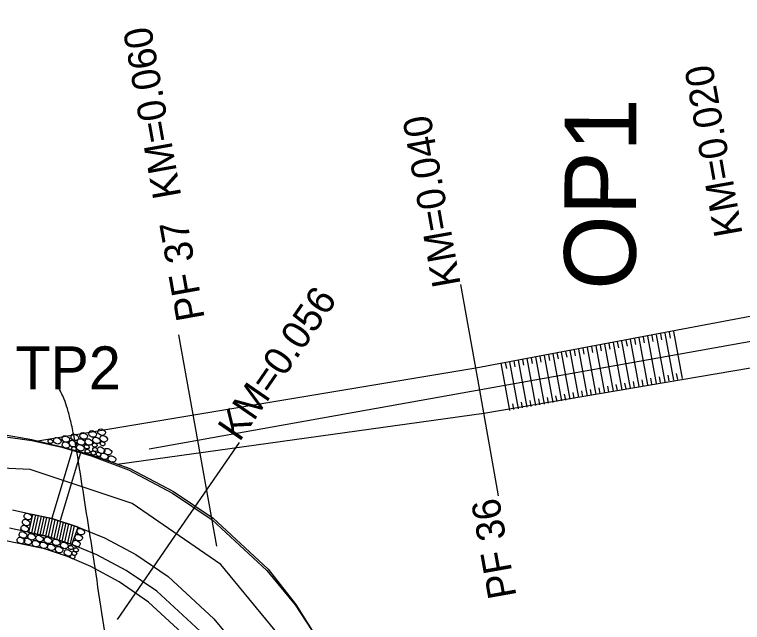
# Model space of a CAD drawing. Extents: x -478102 to -473059, y -1117705 to -1114104.
# Drawn here: x -476287.7 to -476236.8, y -1117055.2 to -1117012.7 of the extents above; entities that cross this region are included whole.
import ezdxf

# ---------------------------------------------------------------- set-up
doc = ezdxf.new("R2010")
doc.units = 0
for name, color, linetype in [('cesty', 7, 'Continuous'), ('el_vedeni__VN', 7, 'Continuous'), ('POLYGONY_SITUACE_PF', 7, 'Continuous'), ('POLYGONY_SITUACE_PF_POPISY', 7, 'Continuous'), ('POLYGONY_SITUACE_PO', 7, 'Continuous'), ('TP _navrh', 7, 'Continuous'), ('TP_HS', 7, 'Continuous'), ('Vrstevnice_hlavni', 7, 'Continuous'), ('Vrstevnice_vedlejsi', 7, 'Continuous')]:
    doc.layers.add(name, color=color, linetype=linetype)

msp = doc.modelspace()

# ---------------------------------------------------------------- linework, layer by layer
for p, q in [((-476285.04, -1117047.856), (-476283.635, -1117043.126)), ((-476284.465, -1117048.027), (-476283.06, -1117043.297)), ((-476286.418, -1117047.609), (-476286.693, -1117048.868)), ((-476286.222, -1117047.651), (-476286.498, -1117048.911)), ((-476286.027, -1117047.694), (-476286.302, -1117048.954)), ((-476285.831, -1117047.737), (-476286.107, -1117048.996)), ((-476285.636, -1117047.78), (-476285.912, -1117049.039)), ((-476285.441, -1117047.822), (-476285.716, -1117049.082)), ((-476285.245, -1117047.865), (-476285.521, -1117049.125)), ((-476285.05, -1117047.908), (-476285.325, -1117049.167)), ((-476284.858, -1117047.965), (-476285.13, -1117049.21)), ((-476284.667, -1117048.027), (-476284.944, -1117049.294)), ((-476284.476, -1117048.09), (-476284.753, -1117049.356)), ((-476284.284, -1117048.152), (-476284.561, -1117049.419)), ((-476284.093, -1117048.214), (-476284.37, -1117049.481)), ((-476283.902, -1117048.276), (-476284.179, -1117049.543)), ((-476283.711, -1117048.338), (-476283.988, -1117049.605)), ((-476283.52, -1117048.401), (-476283.797, -1117049.667))]:
    msp.add_line(p, q)
for points in [[(-476243.78, -1117035.233), (-476243.704, -1117035.643)], [(-476243.479, -1117035.177), (-476242.873, -1117038.464)], [(-476243.178, -1117035.122), (-476243.102, -1117035.532)], [(-476242.877, -1117035.066), (-476242.271, -1117038.353)], [(-476242.576, -1117035.011), (-476242.5, -1117035.422)], [(-476242.275, -1117034.955), (-476241.669, -1117038.242)], [(-476241.974, -1117034.9), (-476241.899, -1117035.311)], [(-476241.673, -1117034.844), (-476241.067, -1117038.131)], [(-476246.488, -1117035.732), (-476245.882, -1117039.018)], [(-476246.187, -1117035.676), (-476246.111, -1117036.087)], [(-476245.886, -1117035.621), (-476245.28, -1117038.907)], [(-476245.585, -1117035.566), (-476245.509, -1117035.976)], [(-476245.284, -1117035.51), (-476244.678, -1117038.796)], [(-476244.983, -1117035.455), (-476244.908, -1117035.865)], [(-476244.682, -1117035.399), (-476244.077, -1117038.685)], [(-476244.382, -1117035.344), (-476244.306, -1117035.754)], [(-476244.081, -1117035.288), (-476243.475, -1117038.574)], [(-476249.196, -1117036.231), (-476249.12, -1117036.642)], [(-476248.895, -1117036.176), (-476248.289, -1117039.462)], [(-476248.594, -1117036.12), (-476248.518, -1117036.531)], [(-476248.293, -1117036.065), (-476247.687, -1117039.351)], [(-476247.992, -1117036.009), (-476247.917, -1117036.42)], [(-476247.691, -1117035.954), (-476247.086, -1117039.24)], [(-476247.391, -1117035.898), (-476247.315, -1117036.309)], [(-476247.09, -1117035.843), (-476246.484, -1117039.129)], [(-476246.789, -1117035.787), (-476246.713, -1117036.198)], [(-476251.904, -1117036.731), (-476251.298, -1117040.017)], [(-476251.603, -1117036.675), (-476251.527, -1117037.086)], [(-476251.302, -1117036.62), (-476250.696, -1117039.906)], [(-476251.001, -1117036.564), (-476250.926, -1117036.975)], [(-476250.701, -1117036.509), (-476250.095, -1117039.795)], [(-476250.4, -1117036.453), (-476250.324, -1117036.864)], [(-476250.099, -1117036.398), (-476249.493, -1117039.684)], [(-476249.798, -1117036.342), (-476249.722, -1117036.753)], [(-476249.497, -1117036.287), (-476248.891, -1117039.573)], [(-476253.71, -1117037.063), (-476253.104, -1117040.35)], [(-476253.409, -1117037.008), (-476253.333, -1117037.419)], [(-476253.108, -1117036.952), (-476252.502, -1117040.239)], [(-476252.807, -1117036.897), (-476252.731, -1117037.308)], [(-476252.506, -1117036.842), (-476251.9, -1117040.128)], [(-476252.205, -1117036.786), (-476252.129, -1117037.197)], [(-476241.368, -1117038.186), (-476241.444, -1117037.775)], [(-476243.776, -1117038.63), (-476243.851, -1117038.219)], [(-476243.174, -1117038.519), (-476243.25, -1117038.108)], [(-476242.572, -1117038.408), (-476242.648, -1117037.997)], [(-476241.97, -1117038.297), (-476242.046, -1117037.886)], [(-476246.785, -1117039.185), (-476246.86, -1117038.774)], [(-476246.183, -1117039.074), (-476246.259, -1117038.663)], [(-476245.581, -1117038.963), (-476245.657, -1117038.552)], [(-476244.979, -1117038.852), (-476245.055, -1117038.441)], [(-476244.377, -1117038.741), (-476244.453, -1117038.33)], [(-476249.192, -1117039.629), (-476249.268, -1117039.218)], [(-476248.59, -1117039.518), (-476248.666, -1117039.107)], [(-476247.988, -1117039.407), (-476248.064, -1117038.996)], [(-476247.386, -1117039.296), (-476247.462, -1117038.885)], [(-476252.201, -1117040.183), (-476252.277, -1117039.773)], [(-476251.599, -1117040.072), (-476251.675, -1117039.662)], [(-476250.997, -1117039.961), (-476251.073, -1117039.551)], [(-476250.396, -1117039.85), (-476250.471, -1117039.44)], [(-476249.794, -1117039.74), (-476249.869, -1117039.329)], [(-476252.803, -1117040.294), (-476252.878, -1117039.883)]]:
    msp.add_lwpolyline(points)
msp.add_lwpolyline([(-476285.005, -1117047.917), (-476286.418, -1117047.609), (-476286.693, -1117048.868), (-476285.356, -1117049.16), (-476283.675, -1117049.707), (-476283.228, -1117048.496)], close=True)
for points in [[(-476282.414, -1117041.798), (-476282.487, -1117042.014), (-476282.247, -1117042.215), (-476282.036, -1117042.166), (-476281.955, -1117041.994), (-476282.052, -1117041.865), (-476282.341, -1117041.771), (-476282.414, -1117041.798)], [(-476281.786, -1117041.678), (-476281.859, -1117041.894), (-476281.62, -1117042.094), (-476281.409, -1117042.046), (-476281.327, -1117041.874), (-476281.424, -1117041.745), (-476281.713, -1117041.651), (-476281.786, -1117041.678)], [(-476285.292, -1117042.386), (-476285.338, -1117042.524), (-476285.185, -1117042.653), (-476285.05, -1117042.622), (-476284.998, -1117042.512), (-476285.06, -1117042.429), (-476285.245, -1117042.369), (-476285.292, -1117042.386)], [(-476284.885, -1117042.281), (-476284.958, -1117042.497), (-476284.719, -1117042.697), (-476284.508, -1117042.649), (-476284.427, -1117042.477), (-476284.523, -1117042.347), (-476284.812, -1117042.254), (-476284.885, -1117042.281)], [(-476284.287, -1117042.149), (-476284.36, -1117042.365), (-476284.121, -1117042.566), (-476283.91, -1117042.517), (-476283.829, -1117042.345), (-476283.925, -1117042.216), (-476284.215, -1117042.122), (-476284.287, -1117042.149)], [(-476283.66, -1117042.038), (-476283.733, -1117042.254), (-476283.494, -1117042.455), (-476283.283, -1117042.406), (-476283.201, -1117042.235), (-476283.298, -1117042.105), (-476283.587, -1117042.011), (-476283.66, -1117042.038)], [(-476283.228, -1117042.361), (-476283.301, -1117042.577), (-476283.062, -1117042.778), (-476282.851, -1117042.73), (-476282.769, -1117042.558), (-476282.866, -1117042.428), (-476283.155, -1117042.335), (-476283.228, -1117042.361)], [(-476283.041, -1117041.936), (-476283.114, -1117042.153), (-476282.875, -1117042.353), (-476282.664, -1117042.305), (-476282.583, -1117042.133), (-476282.679, -1117042.003), (-476282.969, -1117041.91), (-476283.041, -1117041.936)], [(-476282.681, -1117042.361), (-476282.754, -1117042.577), (-476282.515, -1117042.778), (-476282.304, -1117042.73), (-476282.223, -1117042.558), (-476282.319, -1117042.428), (-476282.609, -1117042.335), (-476282.681, -1117042.361)], [(-476282.146, -1117042.25), (-476282.219, -1117042.467), (-476281.98, -1117042.667), (-476281.769, -1117042.619), (-476281.687, -1117042.447), (-476281.784, -1117042.317), (-476282.073, -1117042.224), (-476282.146, -1117042.25)], [(-476281.647, -1117042.14), (-476281.72, -1117042.356), (-476281.481, -1117042.556), (-476281.27, -1117042.508), (-476281.189, -1117042.336), (-476281.285, -1117042.206), (-476281.575, -1117042.113), (-476281.647, -1117042.14)], [(-476284.278, -1117042.574), (-476284.351, -1117042.79), (-476284.112, -1117042.99), (-476283.901, -1117042.942), (-476283.82, -1117042.77), (-476283.916, -1117042.641), (-476284.205, -1117042.547), (-476284.278, -1117042.574)], [(-476283.798, -1117042.472), (-476283.871, -1117042.688), (-476283.632, -1117042.889), (-476283.421, -1117042.841), (-476283.34, -1117042.669), (-476283.436, -1117042.539), (-476283.725, -1117042.445), (-476283.798, -1117042.472)], [(-476283.641, -1117042.903), (-476283.687, -1117043.042), (-476283.534, -1117043.17), (-476283.399, -1117043.139), (-476283.347, -1117043.029), (-476283.409, -1117042.946), (-476283.594, -1117042.886), (-476283.641, -1117042.903)], [(-476283.272, -1117042.768), (-476283.345, -1117042.984), (-476283.106, -1117043.184), (-476282.895, -1117043.136), (-476282.813, -1117042.964), (-476282.91, -1117042.834), (-476283.199, -1117042.741), (-476283.272, -1117042.768)], [(-476282.76, -1117042.766), (-476282.807, -1117042.904), (-476282.653, -1117043.033), (-476282.518, -1117043.002), (-476282.466, -1117042.892), (-476282.528, -1117042.809), (-476282.713, -1117042.749), (-476282.76, -1117042.766)], [(-476282.195, -1117042.645), (-476282.242, -1117042.783), (-476282.089, -1117042.911), (-476281.954, -1117042.88), (-476281.902, -1117042.77), (-476281.964, -1117042.687), (-476282.149, -1117042.628), (-476282.195, -1117042.645)], [(-476281.647, -1117042.55), (-476281.694, -1117042.688), (-476281.541, -1117042.816), (-476281.406, -1117042.785), (-476281.353, -1117042.675), (-476281.415, -1117042.592), (-476281.6, -1117042.533), (-476281.647, -1117042.55)], [(-476282.707, -1117043.083), (-476282.754, -1117043.221), (-476282.601, -1117043.349), (-476282.466, -1117043.319), (-476282.414, -1117043.209), (-476282.475, -1117043.126), (-476282.661, -1117043.066), (-476282.707, -1117043.083)], [(-476282.29, -1117043.199), (-476282.337, -1117043.337), (-476282.184, -1117043.466), (-476282.049, -1117043.435), (-476281.997, -1117043.325), (-476282.059, -1117043.242), (-476282.244, -1117043.182), (-476282.29, -1117043.199)], [(-476282.169, -1117042.961), (-476282.216, -1117043.1), (-476282.063, -1117043.228), (-476281.928, -1117043.197), (-476281.876, -1117043.087), (-476281.937, -1117043.004), (-476282.123, -1117042.944), (-476282.169, -1117042.961)], [(-476281.926, -1117043.296), (-476281.972, -1117043.434), (-476281.819, -1117043.562), (-476281.684, -1117043.531), (-476281.632, -1117043.421), (-476281.694, -1117043.338), (-476281.879, -1117043.279), (-476281.926, -1117043.296)], [(-476281.823, -1117042.934), (-476281.896, -1117043.15), (-476281.657, -1117043.351), (-476281.446, -1117043.302), (-476281.364, -1117043.13), (-476281.461, -1117043.001), (-476281.75, -1117042.907), (-476281.823, -1117042.934)], [(-476281.601, -1117043.359), (-476281.674, -1117043.575), (-476281.435, -1117043.775), (-476281.224, -1117043.727), (-476281.143, -1117043.555), (-476281.239, -1117043.426), (-476281.529, -1117043.332), (-476281.601, -1117043.359)], [(-476281.352, -1117043.036), (-476281.425, -1117043.252), (-476281.186, -1117043.452), (-476280.975, -1117043.404), (-476280.894, -1117043.232), (-476280.99, -1117043.102), (-476281.279, -1117043.009), (-476281.352, -1117043.036)], [(-476281.061, -1117043.555), (-476281.134, -1117043.771), (-476280.895, -1117043.971), (-476280.684, -1117043.923), (-476280.602, -1117043.751), (-476280.699, -1117043.622), (-476280.988, -1117043.528), (-476281.061, -1117043.555)], [(-476287.061, -1117047.985), (-476287.134, -1117048.202), (-476286.895, -1117048.402), (-476286.684, -1117048.354), (-476286.603, -1117048.182), (-476286.699, -1117048.052), (-476286.988, -1117047.959), (-476287.061, -1117047.985)], [(-476286.94, -1117047.565), (-476287.013, -1117047.781), (-476286.774, -1117047.982), (-476286.563, -1117047.933), (-476286.482, -1117047.762), (-476286.578, -1117047.632), (-476286.867, -1117047.538), (-476286.94, -1117047.565)], [(-476287.155, -1117048.405), (-476287.228, -1117048.621), (-476286.988, -1117048.821), (-476286.777, -1117048.773), (-476286.696, -1117048.601), (-476286.793, -1117048.471), (-476287.082, -1117048.378), (-476287.155, -1117048.405)], [(-476287.276, -1117048.848), (-476287.349, -1117049.065), (-476287.11, -1117049.265), (-476286.899, -1117049.217), (-476286.817, -1117049.045), (-476286.914, -1117048.915), (-476287.203, -1117048.822), (-476287.276, -1117048.848)], [(-476286.681, -1117048.984), (-476286.754, -1117049.2), (-476286.514, -1117049.4), (-476286.304, -1117049.352), (-476286.222, -1117049.18), (-476286.319, -1117049.05), (-476286.608, -1117048.957), (-476286.681, -1117048.984)], [(-476283.241, -1117048.624), (-476283.314, -1117048.84), (-476283.075, -1117049.041), (-476282.864, -1117048.993), (-476282.782, -1117048.821), (-476282.879, -1117048.691), (-476283.168, -1117048.597), (-476283.241, -1117048.624)], [(-476287.429, -1117049.239), (-476287.502, -1117049.455), (-476287.263, -1117049.656), (-476287.052, -1117049.607), (-476286.97, -1117049.435), (-476287.067, -1117049.306), (-476287.356, -1117049.212), (-476287.429, -1117049.239)], [(-476286.944, -1117049.308), (-476287.017, -1117049.524), (-476286.777, -1117049.724), (-476286.566, -1117049.676), (-476286.485, -1117049.504), (-476286.582, -1117049.374), (-476286.871, -1117049.281), (-476286.944, -1117049.308)], [(-476286.379, -1117049.461), (-476286.452, -1117049.677), (-476286.213, -1117049.877), (-476286.002, -1117049.829), (-476285.921, -1117049.657), (-476286.017, -1117049.527), (-476286.307, -1117049.434), (-476286.379, -1117049.461)], [(-476286.126, -1117049.102), (-476286.199, -1117049.318), (-476285.96, -1117049.518), (-476285.749, -1117049.47), (-476285.668, -1117049.298), (-476285.764, -1117049.169), (-476286.053, -1117049.075), (-476286.126, -1117049.102)], [(-476285.53, -1117049.223), (-476285.603, -1117049.439), (-476285.364, -1117049.64), (-476285.153, -1117049.592), (-476285.072, -1117049.42), (-476285.168, -1117049.29), (-476285.457, -1117049.196), (-476285.53, -1117049.223)], [(-476284.96, -1117049.371), (-476285.033, -1117049.587), (-476284.794, -1117049.788), (-476284.583, -1117049.739), (-476284.502, -1117049.567), (-476284.598, -1117049.438), (-476284.888, -1117049.344), (-476284.96, -1117049.371)], [(-476283.552, -1117049.453), (-476283.625, -1117049.669), (-476283.386, -1117049.869), (-476283.175, -1117049.821), (-476283.094, -1117049.649), (-476283.19, -1117049.52), (-476283.479, -1117049.426), (-476283.552, -1117049.453)], [(-476283.399, -1117049.041), (-476283.472, -1117049.257), (-476283.233, -1117049.458), (-476283.022, -1117049.409), (-476282.941, -1117049.238), (-476283.037, -1117049.108), (-476283.326, -1117049.014), (-476283.399, -1117049.041)], [(-476285.841, -1117049.577), (-476285.914, -1117049.793), (-476285.675, -1117049.993), (-476285.464, -1117049.945), (-476285.383, -1117049.773), (-476285.479, -1117049.644), (-476285.769, -1117049.55), (-476285.841, -1117049.577)], [(-476285.303, -1117049.714), (-476285.376, -1117049.93), (-476285.137, -1117050.131), (-476284.926, -1117050.082), (-476284.845, -1117049.91), (-476284.941, -1117049.781), (-476285.231, -1117049.687), (-476285.303, -1117049.714)], [(-476284.755, -1117049.878), (-476284.828, -1117050.094), (-476284.589, -1117050.294), (-476284.378, -1117050.246), (-476284.296, -1117050.074), (-476284.393, -1117049.944), (-476284.682, -1117049.851), (-476284.755, -1117049.878)], [(-476284.391, -1117049.587), (-476284.464, -1117049.803), (-476284.225, -1117050.004), (-476284.014, -1117049.956), (-476283.932, -1117049.784), (-476284.029, -1117049.654), (-476284.318, -1117049.561), (-476284.391, -1117049.587)], [(-476283.869, -1117049.803), (-476283.915, -1117049.941), (-476283.762, -1117050.069), (-476283.627, -1117050.039), (-476283.575, -1117049.929), (-476283.637, -1117049.846), (-476283.822, -1117049.786), (-476283.869, -1117049.803)], [(-476283.511, -1117049.965), (-476283.558, -1117050.103), (-476283.405, -1117050.231), (-476283.27, -1117050.2), (-476283.218, -1117050.09), (-476283.28, -1117050.007), (-476283.465, -1117049.948), (-476283.511, -1117049.965)], [(-476284.138, -1117050.105), (-476284.211, -1117050.321), (-476283.971, -1117050.521), (-476283.76, -1117050.473), (-476283.679, -1117050.301), (-476283.775, -1117050.171), (-476284.065, -1117050.078), (-476284.138, -1117050.105)], [(-476283.74, -1117050.444), (-476283.787, -1117050.583), (-476283.634, -1117050.711), (-476283.499, -1117050.68), (-476283.447, -1117050.57), (-476283.509, -1117050.487), (-476283.694, -1117050.427), (-476283.74, -1117050.444)], [(-476283.624, -1117050.205), (-476283.671, -1117050.344), (-476283.518, -1117050.472), (-476283.383, -1117050.441), (-476283.33, -1117050.331), (-476283.392, -1117050.248), (-476283.577, -1117050.188), (-476283.624, -1117050.205)]]:
    msp.add_spline(points, degree=3)
at = {"layer": 'cesty'}
for p, q in [((-476288.604, -1117042.159), (-476286.477, -1117042.455)), ((-476288.59, -1117042.021), (-476286.463, -1117042.376)), ((-476286.477, -1117042.455), (-476284.378, -1117042.908)), ((-476286.463, -1117042.376), (-476284.374, -1117042.894)), ((-476284.378, -1117042.908), (-476282.318, -1117043.515)), ((-476284.374, -1117042.894), (-476282.3, -1117043.463)), ((-476282.318, -1117043.515), (-476279.727, -1117044.491)), ((-476282.3, -1117043.463), (-476279.635, -1117044.419)), ((-476279.727, -1117044.491), (-476276.645, -1117046.126)), ((-476279.635, -1117044.419), (-476276.577, -1117046.014)), ((-476276.645, -1117046.126), (-476273.889, -1117047.998)), ((-476276.577, -1117046.014), (-476273.801, -1117047.883)), ((-476287.83, -1117047.3), (-476285.005, -1117047.917)), ((-476285.005, -1117047.917), (-476283.228, -1117048.496)), ((-476273.801, -1117047.883), (-476269.975, -1117051.447)), ((-476273.889, -1117047.998), (-476270.059, -1117051.524)), ((-476285.356, -1117049.16), (-476288.03, -1117048.576)), ((-476283.228, -1117048.496), (-476281.395, -1117049.259)), ((-476283.675, -1117049.707), (-476285.356, -1117049.16)), ((-476281.395, -1117049.259), (-476279.216, -1117050.416)), ((-476281.942, -1117050.429), (-476283.675, -1117049.707)), ((-476279.879, -1117051.525), (-476281.942, -1117050.429)), ((-476279.216, -1117050.416), (-476276.946, -1117051.958)), ((-476269.975, -1117051.447), (-476268.033, -1117053.896)), ((-476277.732, -1117052.983), (-476279.879, -1117051.525)), ((-476276.946, -1117051.958), (-476273.752, -1117054.898)), ((-476270.059, -1117051.524), (-476268.093, -1117053.939)), ((-476274.708, -1117055.766), (-476277.732, -1117052.983)), ((-476268.093, -1117053.939), (-476266.552, -1117056.287)), ((-476268.033, -1117053.896), (-476266.535, -1117056.277)), ((-476273.752, -1117054.898), (-476272.135, -1117056.886))]:
    msp.add_line(p, q, dxfattribs=at)
msp.add_lwpolyline([(-476266.732, -1117074.511), (-476270.768, -1117064.204), (-476271.566, -1117062.212), (-476272.761, -1117059.954), (-476273.936, -1117058.207), (-476275.415, -1117056.411), (-476278.317, -1117053.74), (-476280.366, -1117052.325), (-476282.34, -1117051.259), (-476283.992, -1117050.544), (-476285.595, -1117050.022), (-476288.167, -1117049.481), (-476290.873, -1117049.234), (-476293.603, -1117049.34), (-476293.603, -1117049.34), (-476299.076, -1117049.264)], dxfattribs=at)
at = {"layer": 'el_vedeni__VN'}
for points in [[(-476255.471, -1117037.386), (-476235.819, -1117033.671)], [(-476254.906, -1117040.545), (-476235.187, -1117037.196)], [(-476286.063, -1117042.475), (-476255.471, -1117037.386)], [(-476280.518, -1117044.102), (-476254.906, -1117040.545)]]:
    msp.add_lwpolyline(points, dxfattribs=at)
at = {"layer": 'POLYGONY_SITUACE_PF'}
for points in [[(-476253.872, -1117046.315), (-476255.194, -1117038.933), (-476256.516, -1117031.55)], [(-476273.559, -1117049.84), (-476274.881, -1117042.458), (-476276.203, -1117035.075)], [(-476280.478, -1117054.949), (-476276.224, -1117048.772), (-476271.971, -1117042.595)]]:
    msp.add_lwpolyline(points, dxfattribs=at)
at = {"layer": 'POLYGONY_SITUACE_PO'}
for points in [[(-476215.821, -1117031.882), (-476278.268, -1117043.064)], [(-476250.954, -1117100.054), (-476256.772, -1117095.342), (-476265.518, -1117063.797), (-476268.51, -1117056.912), (-476273.282, -1117051.116), (-476279.465, -1117046.859), (-476286.581, -1117044.469), (-476294.08, -1117044.131), (-476301.427, -1117045.065)]]:
    msp.add_lwpolyline(points, dxfattribs=at)
at = {"layer": 'Vrstevnice_hlavni'}
msp.add_spline([(-476249.493, -1117108.392), (-476249.775, -1117107.699), (-476250.264, -1117106.97), (-476250.958, -1117106.207), (-476251.857, -1117105.408), (-476252.513, -1117105.14), (-476252.925, -1117105.402), (-476253.095, -1117106.195), (-476253.235, -1117107.1), (-476253.347, -1117108.118), (-476253.43, -1117109.248), (-476253.596, -1117109.985), (-476253.847, -1117110.328), (-476254.181, -1117110.278), (-476255.528, -1117110.336), (-476257.887, -1117110.502), (-476261.259, -1117110.776), (-476263.654, -1117110.928), (-476265.074, -1117110.957), (-476265.519, -1117110.863), (-476266.5, -1117108.002), (-476268.017, -1117102.375), (-476270.071, -1117093.98), (-476271.569, -1117088.098), (-476272.511, -1117084.73), (-476272.897, -1117083.874), (-476273.181, -1117083.184), (-476273.365, -1117082.66), (-476273.447, -1117082.301), (-476273.665, -1117081.937), (-476274.021, -1117081.569), (-476274.513, -1117081.196), (-476274.898, -1117080.887), (-476275.174, -1117080.644), (-476275.342, -1117080.466), (-476275.953, -1117078.624), (-476277.006, -1117075.118), (-476278.503, -1117069.948), (-476279.866, -1117064.113), (-476281.094, -1117057.612), (-476282.188, -1117050.447), (-476282.997, -1117045.306), (-476283.52, -1117042.188), (-476283.758, -1117041.094), (-476283.99, -1117040.218), (-476284.216, -1117039.561), (-476284.654, -1117038.684)], degree=3, dxfattribs=at)
at = {"layer": 'Vrstevnice_vedlejsi'}
for points in [[(-476316.243, -1116908.48), (-476314.561, -1116908.998), (-476313.123, -1116909.665), (-476311.928, -1116910.479), (-476310.975, -1116911.441), (-476307.447, -1116912.926), (-476301.342, -1116914.935), (-476292.661, -1116917.468), (-476286.431, -1116920.344), (-476282.653, -1116923.565), (-476281.326, -1116927.13), (-476278.825, -1116928.622), (-476275.148, -1116928.043), (-476270.296, -1116925.391), (-476267.359, -1116923.353), (-476266.337, -1116921.926), (-476267.229, -1116921.113), (-476266.831, -1116920.277), (-476265.141, -1116919.419), (-476262.159, -1116918.539), (-476258.731, -1116917.573), (-476254.857, -1116916.522), (-476250.536, -1116915.385), (-476247.506, -1116914.708), (-476245.767, -1116914.49), (-476245.318, -1116914.73), (-476244.967, -1116914.931), (-476244.714, -1116915.09), (-476244.558, -1116915.209), (-476244.297, -1116915.426), (-476243.929, -1116915.74), (-476243.455, -1116916.152), (-476242.992, -1116916.618), (-476242.539, -1116917.137), (-476242.097, -1116917.711), (-476241.648, -1116918.268), (-476241.19, -1116918.809), (-476240.724, -1116919.335), (-476240.357, -1116919.802), (-476240.09, -1116920.212), (-476239.921, -1116920.565), (-476239.776, -1116920.901), (-476239.653, -1116921.22), (-476239.554, -1116921.522), (-476239.275, -1116922.323), (-476238.817, -1116923.622), (-476238.18, -1116925.419), (-476237.671, -1116926.892), (-476237.289, -1116928.04), (-476237.035, -1116928.865), (-476237.012, -1116929.601), (-476237.222, -1116930.251), (-476237.665, -1116930.812), (-476238.042, -1116931.305), (-476238.354, -1116931.728), (-476238.601, -1116932.083), (-476239.32, -1116932.842), (-476240.511, -1116934.008), (-476242.173, -1116935.579), (-476243.89, -1116939.165), (-476245.66, -1116944.767), (-476247.485, -1116952.383), (-476247.667, -1116959.217), (-476246.206, -1116965.267), (-476243.103, -1116970.535), (-476240.745, -1116976.442), (-476239.133, -1116982.988), (-476238.266, -1116990.175), (-476237.639, -1116995.076), (-476237.25, -1116997.694), (-476237.099, -1116998.028), (-476236.956, -1116998.362), (-476236.818, -1116998.698), (-476236.687, -1116999.033), (-476236.643, -1116999.341), (-476236.684, -1116999.621), (-476236.813, -1116999.873), (-476235.592, -1117002.993), (-476233.023, -1117008.983), (-476229.104, -1117017.842), (-476226.381, -1117023.996), (-476224.854, -1117027.447), (-476224.521, -1117028.193), (-476224.304, -1117028.701), (-476224.204, -1117028.973), (-476224.22, -1117029.007), (-476224.213, -1117029.062), (-476224.183, -1117029.137), (-476224.131, -1117029.234), (-476224.075, -1117029.288), (-476224.014, -1117029.297), (-476223.948, -1117029.262), (-476223.307, -1117029.574), (-476222.09, -1117030.231), (-476220.296, -1117031.233), (-476219.154, -1117032.301), (-476218.662, -1117033.435)], [(-476361.641, -1116910.017), (-476360.991, -1116911.137), (-476360.552, -1116912.67), (-476360.323, -1116914.616), (-476360.306, -1116916.973), (-476360.308, -1116918.585), (-476360.329, -1116919.449), (-476360.369, -1116919.567), (-476360.386, -1116919.663), (-476360.38, -1116919.738), (-476360.35, -1116919.79), (-476360.486, -1116921.699), (-476360.787, -1116925.464), (-476361.254, -1116931.086), (-476361.67, -1116935.051), (-476362.037, -1116937.36), (-476362.353, -1116938.012), (-476362.549, -1116938.736), (-476362.623, -1116939.532), (-476362.576, -1116940.398), (-476362.264, -1116942.869), (-476361.686, -1116946.945), (-476360.843, -1116952.626), (-476360.093, -1116958.73), (-476359.435, -1116965.256), (-476358.871, -1116972.204), (-476358.36, -1116977.092), (-476357.904, -1116979.919), (-476357.501, -1116980.685), (-476356.57, -1116984.99), (-476355.11, -1116992.835), (-476353.122, -1117004.219), (-476351.571, -1117012.905), (-476350.455, -1117018.893), (-476349.776, -1117022.183), (-476349.504, -1117027.698), (-476349.639, -1117035.437), (-476350.182, -1117045.4), (-476350.307, -1117053.191), (-476350.012, -1117058.811), (-476349.298, -1117062.259), (-476350.091, -1117065.67), (-476352.39, -1117069.042), (-476356.195, -1117072.377), (-476359.92, -1117076.705), (-476363.566, -1117082.026), (-476367.131, -1117088.339), (-476371.33, -1117094.641), (-476376.164, -1117100.933), (-476381.631, -1117107.213), (-476386.474, -1117112.181), (-476390.692, -1117115.834), (-476394.286, -1117118.174), (-476397.491, -1117120.393), (-476400.306, -1117122.492), (-476402.732, -1117124.472), (-476402.928, -1117127.738), (-476400.894, -1117132.291), (-476396.631, -1117138.131), (-476389.647, -1117141.585), (-476379.944, -1117142.653), (-476367.521, -1117141.334), (-476355.525, -1117141.406), (-476343.957, -1117142.868), (-476332.816, -1117145.722), (-476324.482, -1117147.814), (-476318.952, -1117149.144), (-476316.229, -1117149.714), (-476310.745, -1117150.91), (-476302.502, -1117152.733), (-476291.498, -1117155.183), (-476284.107, -1117156.821), (-476280.33, -1117157.647), (-476280.165, -1117157.662), (-476279.816, -1117157.743), (-476279.284, -1117157.891), (-476278.569, -1117158.106), (-476278.072, -1117158.306), (-476277.796, -1117158.489), (-476277.739, -1117158.657), (-476277.684, -1117158.815), (-476277.629, -1117158.963), (-476277.576, -1117159.102), (-476277.523, -1117159.234), (-476277.472, -1117159.361), (-476277.423, -1117159.482), (-476277.379, -1117159.591), (-476277.34, -1117159.689), (-476277.307, -1117159.775), (-476277.275, -1117159.863), (-476277.243, -1117159.954), (-476277.212, -1117160.046), (-476277.173, -1117160.139), (-476277.129, -1117160.233), (-476277.078, -1117160.326), (-476277.04, -1117160.421), (-476277.015, -1117160.516)]]:
    msp.add_spline(points, degree=3, dxfattribs=at)

# ---------------------------------------------------------------- texts
at = {"layer": 'POLYGONY_SITUACE_PF_POPISY'}
for s, rotation, p in [('KM=0.060', 100.152, (-476276.028, -1117025.386)), ('KM=0.020', 100.152, (-476236.827, -1117028.037)), ('KM=0.040', 100.152, (-476256.514, -1117031.562)), ('PF 37', 100.152, (-476274.392, -1117033.916)), ('KM=0.056', 55.4518, (-476271.978, -1117042.605)), ('PF 36', 100.152, (-476252.618, -1117053.319))]:
    msp.add_text(s, height=1.9765, rotation=rotation, dxfattribs=at).set_placement(p)
at = {"layer": 'TP _navrh'}
msp.add_text('TP2', height=3, rotation=360, dxfattribs=at).set_placement((-476287.615, -1117038.881))
at = {"layer": 'TP_HS'}
msp.add_text('OP1', height=5, rotation=89.7225, dxfattribs=at).set_placement((-476244.31, -1117031.941))

doc.saveas('drawing.dxf')
